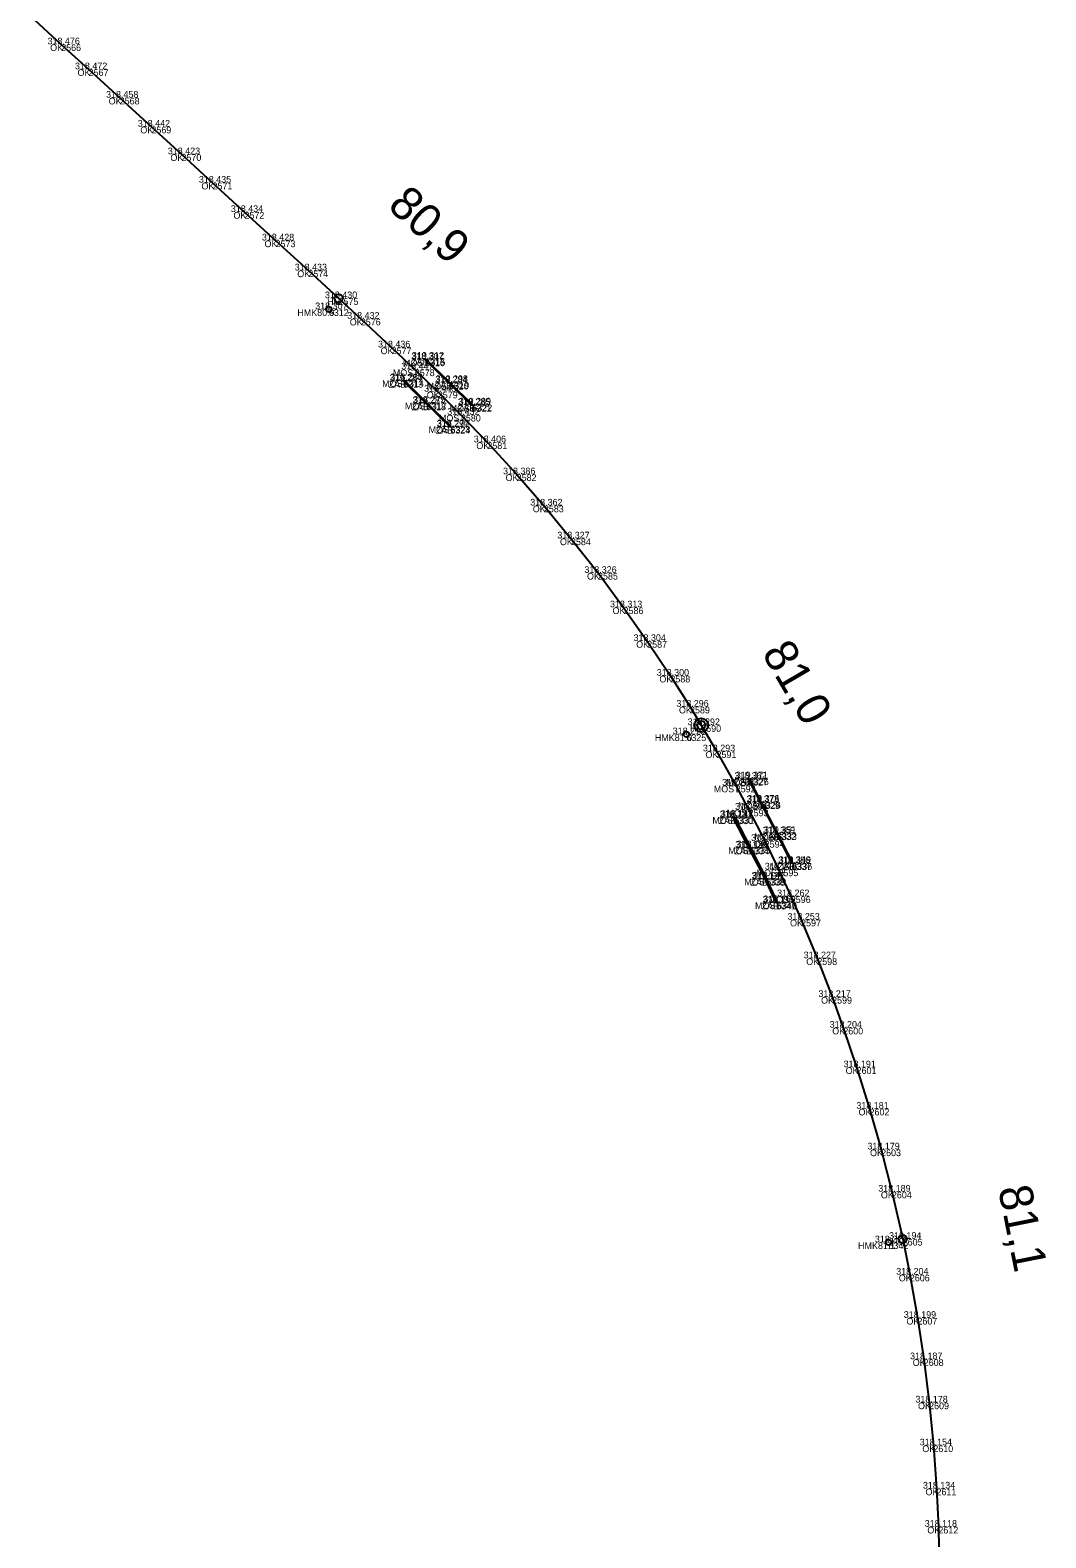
# Model space of a CAD drawing. Extents: x -621782 to -610392, y -1141853 to -1122321.
# Drawn here: x -613991.1 to -613808.5, y -1130998.2 to -1130727.2 of the extents above; entities that cross this region are included whole.
import ezdxf

# ---------------------------------------------------------------- set-up
doc = ezdxf.new("R2010")
doc.units = 0
for name, color, linetype in [('Vrstva 1', 7, 'Continuous'), ('Vrstva 17', 7, 'Continuous'), ('Vrstva 18', 7, 'Continuous'), ('Vrstva 60', 7, 'Continuous'), ('Vrstva 61', 7, 'Continuous'), ('Vrstva 62', 7, 'Continuous'), ('Vrstva 7', 7, 'Continuous')]:
    doc.layers.add(name, color=color, linetype=linetype)

msp = doc.modelspace()

# ---------------------------------------------------------------- linework, layer by layer
at = {"layer": 'Vrstva 1'}
msp.add_lwpolyline([(-613991.08, -1130724.65), (-613985.5, -1130729.75), (-613980.57, -1130734.23), (-613974.98, -1130739.35), (-613969.28, -1130744.55), (-613963.88, -1130749.51), (-613958.3, -1130754.62), (-613952.55, -1130759.89), (-613946.96, -1130765.01), (-613941.07, -1130770.4), (-613935.64, -1130775.39), (-613931.64, -1130779.08), (-613926.1, -1130784.24), (-613921.93, -1130788.2), (-613917.8, -1130792.2), (-613913.65, -1130796.35), (-613908.89, -1130801.3), (-613903.62, -1130807.05), (-613898.73, -1130812.66), (-613893.86, -1130818.58), (-613889, -1130824.77), (-613884.4, -1130830.97), (-613880.16, -1130837.02), (-613875.99, -1130843.26), (-613872.46, -1130848.83), (-613870.44, -1130852.14), (-613867.7, -1130856.84), (-613864.24, -1130863.01), (-613861.92, -1130867.32), (-613859.04, -1130872.96), (-613856.56, -1130878.09), (-613854.35, -1130882.9), (-613852.49, -1130887.11), (-613849.59, -1130894.05), (-613846.92, -1130901), (-613844.91, -1130906.53), (-613842.51, -1130913.64), (-613840.19, -1130921.1), (-613838.11, -1130928.42), (-613836.17, -1130936), (-613834.23, -1130944.49), (-613832.95, -1130950.92), (-613831.58, -1130958.69), (-613830.45, -1130966.13), (-613829.48, -1130973.91), (-613828.72, -1130981.62), (-613828.15, -1130989.38), (-613827.82, -1130996.25), (-613827.71, -1131000.22)], dxfattribs=at)
at = {"layer": 'Vrstva 17'}
for points in [[(-613920.01, -1130786.27), (-613915.73, -1130790.46), (-613911.59, -1130794.5)], [(-613915.55, -1130798.53), (-613919.89, -1130794.32), (-613924.01, -1130790.27)], [(-613861.88, -1130861.7), (-613859.73, -1130865.9), (-613856.82, -1130871.55), (-613854.07, -1130876.92)], [(-613856.98, -1130884.06), (-613858.95, -1130879.78), (-613861.88, -1130874.18), (-613864.69, -1130868.73)]]:
    msp.add_lwpolyline(points, dxfattribs=at)
at = {"layer": 'Vrstva 18'}
for points in [[(-613911.73, -1130794.61), (-613915.84, -1130790.6), (-613920.11, -1130786.41)], [(-613923.86, -1130790.13), (-613919.77, -1130794.18), (-613915.5, -1130798.42)], [(-613862.03, -1130861.8), (-613859.86, -1130866.01), (-613856.94, -1130871.6), (-613854.21, -1130876.99)], [(-613864.49, -1130868.64), (-613861.64, -1130874.1), (-613858.75, -1130879.72), (-613856.82, -1130883.97)]]:
    msp.add_lwpolyline(points, dxfattribs=at)
at = {"layer": 'Vrstva 60'}
for p, q in [((-613985.5, -1130729.75), (-613985.5, -1130729.75)), ((-613980.57, -1130734.23), (-613980.57, -1130734.23)), ((-613974.98, -1130739.35), (-613974.98, -1130739.35)), ((-613969.28, -1130744.55), (-613969.28, -1130744.55)), ((-613963.88, -1130749.51), (-613963.88, -1130749.51)), ((-613958.3, -1130754.62), (-613958.3, -1130754.62)), ((-613952.55, -1130759.89), (-613952.55, -1130759.89)), ((-613946.96, -1130765.01), (-613946.96, -1130765.01)), ((-613941.07, -1130770.4), (-613941.07, -1130770.4)), ((-613937.38, -1130777.37), (-613937.38, -1130777.37)), ((-613935.64, -1130775.39), (-613935.64, -1130775.39)), ((-613931.64, -1130779.08), (-613931.64, -1130779.08)), ((-613926.1, -1130784.24), (-613926.1, -1130784.24)), ((-613921.93, -1130788.2), (-613921.93, -1130788.2)), ((-613920.11, -1130786.41), (-613920.11, -1130786.41)), ((-613920.01, -1130786.27), (-613920.01, -1130786.27)), ((-613924.01, -1130790.27), (-613924.01, -1130790.27)), ((-613923.86, -1130790.13), (-613923.86, -1130790.13)), ((-613915.84, -1130790.6), (-613915.84, -1130790.6)), ((-613915.73, -1130790.46), (-613915.73, -1130790.46)), ((-613919.77, -1130794.18), (-613919.77, -1130794.18)), ((-613917.8, -1130792.2), (-613917.8, -1130792.2)), ((-613919.89, -1130794.32), (-613919.89, -1130794.32)), ((-613913.65, -1130796.35), (-613913.65, -1130796.35)), ((-613911.73, -1130794.61), (-613911.73, -1130794.61)), ((-613911.59, -1130794.5), (-613911.59, -1130794.5)), ((-613915.55, -1130798.53), (-613915.55, -1130798.53)), ((-613915.5, -1130798.42), (-613915.5, -1130798.42)), ((-613908.89, -1130801.3), (-613908.89, -1130801.3)), ((-613903.62, -1130807.05), (-613903.62, -1130807.05)), ((-613898.73, -1130812.66), (-613898.73, -1130812.66)), ((-613893.86, -1130818.58), (-613893.86, -1130818.58)), ((-613889, -1130824.77), (-613889, -1130824.77)), ((-613884.4, -1130830.97), (-613884.4, -1130830.97)), ((-613880.16, -1130837.02), (-613880.16, -1130837.02)), ((-613875.99, -1130843.26), (-613875.99, -1130843.26)), ((-613872.46, -1130848.83), (-613872.46, -1130848.83)), ((-613873.12, -1130853.78), (-613873.12, -1130853.78)), ((-613870.44, -1130852.14), (-613870.44, -1130852.14)), ((-613867.7, -1130856.84), (-613867.7, -1130856.84)), ((-613862.03, -1130861.8), (-613862.03, -1130861.8)), ((-613861.88, -1130861.7), (-613861.88, -1130861.7)), ((-613864.24, -1130863.01), (-613864.24, -1130863.01)), ((-613861.92, -1130867.32), (-613861.92, -1130867.32)), ((-613859.86, -1130866.01), (-613859.86, -1130866.01)), ((-613859.73, -1130865.9), (-613859.73, -1130865.9)), ((-613864.69, -1130868.73), (-613864.69, -1130868.73)), ((-613864.49, -1130868.64), (-613864.49, -1130868.64)), ((-613856.94, -1130871.6), (-613856.94, -1130871.6)), ((-613856.82, -1130871.55), (-613856.82, -1130871.55)), ((-613861.88, -1130874.18), (-613861.88, -1130874.18)), ((-613861.64, -1130874.1), (-613861.64, -1130874.1)), ((-613859.04, -1130872.96), (-613859.04, -1130872.96)), ((-613856.56, -1130878.09), (-613856.56, -1130878.09)), ((-613854.21, -1130876.99), (-613854.21, -1130876.99)), ((-613854.07, -1130876.92), (-613854.07, -1130876.92)), ((-613858.95, -1130879.78), (-613858.95, -1130879.78)), ((-613858.75, -1130879.72), (-613858.75, -1130879.72)), ((-613854.35, -1130882.9), (-613854.35, -1130882.9)), ((-613856.98, -1130884.06), (-613856.98, -1130884.06)), ((-613856.82, -1130883.97), (-613856.82, -1130883.97)), ((-613852.49, -1130887.11), (-613852.49, -1130887.11)), ((-613849.59, -1130894.05), (-613849.59, -1130894.05)), ((-613846.92, -1130901), (-613846.92, -1130901)), ((-613844.91, -1130906.53), (-613844.91, -1130906.53)), ((-613842.51, -1130913.64), (-613842.51, -1130913.64)), ((-613840.19, -1130921.1), (-613840.19, -1130921.1)), ((-613838.11, -1130928.42), (-613838.11, -1130928.42)), ((-613836.17, -1130936), (-613836.17, -1130936)), ((-613836.78, -1130945.12), (-613836.78, -1130945.12)), ((-613834.23, -1130944.49), (-613834.23, -1130944.49)), ((-613832.95, -1130950.92), (-613832.95, -1130950.92)), ((-613831.58, -1130958.69), (-613831.58, -1130958.69)), ((-613830.45, -1130966.13), (-613830.45, -1130966.13)), ((-613829.48, -1130973.91), (-613829.48, -1130973.91)), ((-613828.72, -1130981.62), (-613828.72, -1130981.62)), ((-613828.15, -1130989.38), (-613828.15, -1130989.38)), ((-613827.82, -1130996.25), (-613827.82, -1130996.25))]:
    msp.add_line(p, q, dxfattribs=at)
at = {"layer": 'Vrstva 7'}
for p, q in [((-613937.42, -1130777.33), (-613937.34, -1130777.4)), ((-613873.14, -1130853.73), (-613873.09, -1130853.82)), ((-613836.79, -1130945.07), (-613836.77, -1130945.17))]:
    msp.add_line(p, q, dxfattribs=at)
for centre, radius in [((-613935.64, -1130775.39), 0.75), ((-613937.38, -1130777.37), 0.5), ((-613870.44, -1130852.14), 1.25), ((-613873.12, -1130853.78), 0.5), ((-613870.44, -1130852.14), 0.752), ((-613836.78, -1130945.12), 0.5), ((-613834.23, -1130944.49), 0.75)]:
    msp.add_circle(centre, radius, dxfattribs=at)

# ---------------------------------------------------------------- texts
at = {"layer": 'Vrstva 60'}
for s, p in [('2566', (-613985.5, -1130730.95)), ('2567', (-613980.57, -1130735.43)), ('2568', (-613974.98, -1130740.55)), ('2569', (-613969.28, -1130745.75)), ('2570', (-613963.88, -1130750.71)), ('2571', (-613958.3, -1130755.82)), ('2572', (-613952.55, -1130761.09)), ('2573', (-613946.96, -1130766.21)), ('2574', (-613941.07, -1130771.6)), ('6312', (-613937.38, -1130778.57)), ('2575', (-613935.64, -1130776.59)), ('2576', (-613931.64, -1130780.28)), ('2577', (-613926.1, -1130785.44)), ('2578', (-613921.93, -1130789.4)), ('6316', (-613920.11, -1130787.61)), ('6315', (-613920.01, -1130787.47)), ('6313', (-613924.01, -1130791.47)), ('6314', (-613923.86, -1130791.33)), ('6320', (-613915.84, -1130791.8)), ('6319', (-613915.73, -1130791.66)), ('6318', (-613919.89, -1130795.52)), ('6317', (-613919.77, -1130795.38)), ('2579', (-613917.8, -1130793.4)), ('2580', (-613913.65, -1130797.55)), ('6321', (-613911.73, -1130795.81)), ('6322', (-613911.59, -1130795.7)), ('6324', (-613915.55, -1130799.73)), ('6323', (-613915.5, -1130799.61)), ('2581', (-613908.89, -1130802.5)), ('2582', (-613903.62, -1130808.25)), ('2583', (-613898.73, -1130813.86)), ('2584', (-613893.86, -1130819.78)), ('2585', (-613889, -1130825.97)), ('2586', (-613884.4, -1130832.17)), ('2587', (-613880.16, -1130838.22)), ('2588', (-613875.99, -1130844.46)), ('2589', (-613872.46, -1130850.03)), ('6325', (-613873.12, -1130854.98)), ('2590', (-613870.44, -1130853.34)), ('2591', (-613867.7, -1130858.04)), ('6327', (-613862.03, -1130863)), ('6326', (-613861.88, -1130862.9)), ('2592', (-613864.24, -1130864.21)), ('2593', (-613861.92, -1130868.52)), ('6329', (-613859.86, -1130867.21)), ('6328', (-613859.73, -1130867.1)), ('6330', (-613864.69, -1130869.93)), ('6331', (-613864.49, -1130869.84)), ('6332', (-613856.94, -1130872.8)), ('6333', (-613856.82, -1130872.75)), ('6334', (-613861.88, -1130875.38)), ('6335', (-613861.64, -1130875.3)), ('2594', (-613859.04, -1130874.16)), ('2595', (-613856.56, -1130879.29)), ('6337', (-613854.21, -1130878.19)), ('6336', (-613854.07, -1130878.12)), ('6338', (-613858.95, -1130880.98)), ('6339', (-613858.75, -1130880.92)), ('2596', (-613854.35, -1130884.1)), ('6341', (-613856.98, -1130885.27)), ('6340', (-613856.82, -1130885.17)), ('2597', (-613852.49, -1130888.31)), ('2598', (-613849.59, -1130895.25)), ('2599', (-613846.92, -1130902.2)), ('2600', (-613844.91, -1130907.73)), ('2601', (-613842.51, -1130914.84)), ('2602', (-613840.19, -1130922.3)), ('2603', (-613838.11, -1130929.62)), ('2604', (-613836.17, -1130937.2)), ('6342', (-613836.78, -1130946.32)), ('2605', (-613834.23, -1130945.69)), ('2606', (-613832.95, -1130952.12)), ('2607', (-613831.58, -1130959.89)), ('2608', (-613830.45, -1130967.33)), ('2609', (-613829.48, -1130975.11)), ('2610', (-613828.72, -1130982.82)), ('2611', (-613828.15, -1130990.58)), ('2612', (-613827.82, -1130997.45))]:
    msp.add_text(s, height=1.2, dxfattribs=at).set_placement(p)
at = {"layer": 'Vrstva 61'}
for s, p in [('318.476', (-613987.95, -1130729.75)), ('318.472', (-613983.02, -1130734.23)), ('318.458', (-613977.43, -1130739.35)), ('318.442', (-613971.73, -1130744.55)), ('318.423', (-613966.33, -1130749.51)), ('318.435', (-613960.75, -1130754.62)), ('318.434', (-613955, -1130759.89)), ('318.428', (-613949.42, -1130765.01)), ('318.433', (-613943.52, -1130770.4)), ('318.430', (-613938.09, -1130775.39)), ('318.307', (-613939.83, -1130777.37)), ('318.432', (-613934.08, -1130779.08)), ('318.436', (-613928.55, -1130784.24)), ('318.307', (-613922.57, -1130786.41)), ('319.312', (-613922.46, -1130786.27)), ('318.447', (-613924.38, -1130788.2)), ('319.284', (-613926.46, -1130790.27)), ('318.263', (-613926.31, -1130790.13)), ('318.445', (-613920.26, -1130792.2)), ('318.284', (-613918.29, -1130790.6)), ('319.298', (-613918.19, -1130790.46)), ('319.287', (-613922.35, -1130794.32)), ('318.275', (-613922.22, -1130794.18)), ('318.285', (-613914.19, -1130794.61)), ('319.289', (-613914.04, -1130794.5)), ('318.432', (-613916.1, -1130796.35)), ('319.290', (-613918, -1130798.53)), ('318.277', (-613917.95, -1130798.42)), ('318.406', (-613911.34, -1130801.3)), ('318.386', (-613906.07, -1130807.05)), ('318.362', (-613901.18, -1130812.66)), ('318.327', (-613896.31, -1130818.58)), ('318.326', (-613891.45, -1130824.77)), ('318.313', (-613886.85, -1130830.97)), ('318.304', (-613882.61, -1130837.02)), ('318.300', (-613878.44, -1130843.26)), ('318.296', (-613874.91, -1130848.83)), ('318.292', (-613872.89, -1130852.14)), ('318.213', (-613875.57, -1130853.78)), ('318.293', (-613870.15, -1130856.84)), ('318.294', (-613866.69, -1130863.01)), ('318.362', (-613864.48, -1130861.8)), ('319.371', (-613864.24, -1130861.7)), ('319.376', (-613862.18, -1130865.9)), ('318.147', (-613866.94, -1130868.64)), ('318.294', (-613864.37, -1130867.32)), ('318.373', (-613862.31, -1130866.01)), ('319.133', (-613867.14, -1130868.73)), ('318.146', (-613864.09, -1130874.1)), ('318.286', (-613861.49, -1130872.96)), ('318.369', (-613859.39, -1130871.6)), ('319.351', (-613859.17, -1130871.55)), ('319.139', (-613864.33, -1130874.18)), ('318.278', (-613859.02, -1130878.09)), ('318.356', (-613856.66, -1130876.99)), ('319.349', (-613856.52, -1130876.92)), ('319.127', (-613861.41, -1130879.78)), ('318.142', (-613861.2, -1130879.72)), ('319.115', (-613859.44, -1130884.06)), ('318.169', (-613859.28, -1130883.97)), ('318.262', (-613856.8, -1130882.9)), ('318.253', (-613854.94, -1130887.11)), ('318.227', (-613852.04, -1130894.05)), ('318.217', (-613849.37, -1130901)), ('318.204', (-613847.36, -1130906.53)), ('318.191', (-613844.86, -1130913.64)), ('318.181', (-613842.55, -1130921.1)), ('318.179', (-613840.57, -1130928.42)), ('318.189', (-613838.62, -1130936)), ('318.194', (-613836.68, -1130944.49)), ('318.224', (-613839.23, -1130945.12)), ('318.204', (-613835.4, -1130950.92)), ('318.199', (-613834.03, -1130958.69)), ('318.187', (-613832.9, -1130966.13)), ('318.178', (-613831.94, -1130973.91)), ('318.154', (-613831.17, -1130981.62)), ('318.134', (-613830.6, -1130989.38)), ('318.118', (-613830.27, -1130996.25))]:
    msp.add_text(s, height=1.2, dxfattribs=at).set_placement(p)
at = {"layer": 'Vrstva 62'}
for s, p in [('OK', (-613987.48, -1130730.95)), ('OK', (-613982.56, -1130735.43)), ('OK', (-613976.96, -1130740.55)), ('OK', (-613971.27, -1130745.75)), ('OK', (-613965.86, -1130750.71)), ('OK', (-613960.28, -1130755.82)), ('OK', (-613954.53, -1130761.09)), ('OK', (-613948.95, -1130766.21)), ('OK', (-613943.06, -1130771.6)), ('HMK80.9', (-613943.05, -1130778.57)), ('HM', (-613937.67, -1130776.59)), ('OK', (-613933.62, -1130780.28)), ('OK', (-613928.08, -1130785.44)), ('MOST', (-613925.88, -1130789.4)), ('MOST', (-613924.06, -1130787.61)), ('ZAB', (-613922.61, -1130787.47)), ('MOST', (-613927.81, -1130791.33)), ('ZAB', (-613926.61, -1130791.47)), ('MOST', (-613919.79, -1130791.8)), ('ZAB', (-613918.33, -1130791.66)), ('MOST', (-613923.71, -1130795.38)), ('OK', (-613919.79, -1130793.4)), ('ZAB', (-613922.5, -1130795.52)), ('MOST', (-613917.59, -1130797.55)), ('MOST', (-613915.68, -1130795.81)), ('ZAB', (-613914.19, -1130795.7)), ('MOST', (-613919.44, -1130799.61)), ('ZAB', (-613918.15, -1130799.73)), ('OK', (-613910.87, -1130802.5)), ('OK', (-613905.61, -1130808.25)), ('OK', (-613900.72, -1130813.86)), ('OK', (-613895.84, -1130819.78)), ('OK', (-613890.98, -1130825.97)), ('OK', (-613886.39, -1130832.17)), ('OK', (-613882.14, -1130838.22)), ('OK', (-613877.97, -1130844.46)), ('OK', (-613874.45, -1130850.03)), ('HMK81.0', (-613878.78, -1130854.98)), ('HM', (-613872.47, -1130853.34)), ('OK', (-613869.68, -1130858.04)), ('MOST', (-613865.98, -1130863)), ('ZAB', (-613864.48, -1130862.9)), ('MOST', (-613868.19, -1130864.21)), ('MOST', (-613865.87, -1130868.52)), ('MOST', (-613863.8, -1130867.21)), ('ZAB', (-613862.33, -1130867.1)), ('MOST', (-613868.44, -1130869.84)), ('ZAB', (-613867.29, -1130869.93)), ('MOST', (-613860.89, -1130872.8)), ('ZAB', (-613859.42, -1130872.75)), ('MOST', (-613865.58, -1130875.3)), ('ZAB', (-613864.48, -1130875.38)), ('OK', (-613861.02, -1130874.16)), ('MOST', (-613860.51, -1130879.29)), ('MOST', (-613858.16, -1130878.19)), ('ZAB', (-613856.67, -1130878.12)), ('MOST', (-613862.7, -1130880.92)), ('ZAB', (-613861.56, -1130880.98)), ('MOST', (-613858.3, -1130884.1)), ('MOST', (-613860.77, -1130885.17)), ('ZAB', (-613859.58, -1130885.27)), ('OK', (-613854.48, -1130888.31)), ('OK', (-613851.57, -1130895.25)), ('OK', (-613848.9, -1130902.2)), ('OK', (-613846.9, -1130907.73)), ('OK', (-613844.49, -1130914.84)), ('OK', (-613842.17, -1130922.3)), ('OK', (-613840.1, -1130929.62)), ('OK', (-613838.15, -1130937.2)), ('HMK81.1', (-613842.25, -1130946.32)), ('HM', (-613836.26, -1130945.69)), ('OK', (-613834.93, -1130952.12)), ('OK', (-613833.56, -1130959.89)), ('OK', (-613832.43, -1130967.33)), ('OK', (-613831.47, -1130975.11)), ('OK', (-613830.7, -1130982.82)), ('OK', (-613830.13, -1130990.58)), ('OK', (-613829.8, -1130997.45))]:
    msp.add_text(s, height=1.2, dxfattribs=at).set_placement(p)
at = {"layer": 'Vrstva 7'}
for s, rotation, p in [('80,9', 317.3085, (-613927.03, -1130759.06)), ('81,0', 300.2648, (-613859.66, -1130839.17)), ('81,1', 281.2842, (-613817.1, -1130935.45))]:
    msp.add_text(s, height=6, rotation=rotation, dxfattribs=at).set_placement(p)

doc.saveas('drawing.dxf')
